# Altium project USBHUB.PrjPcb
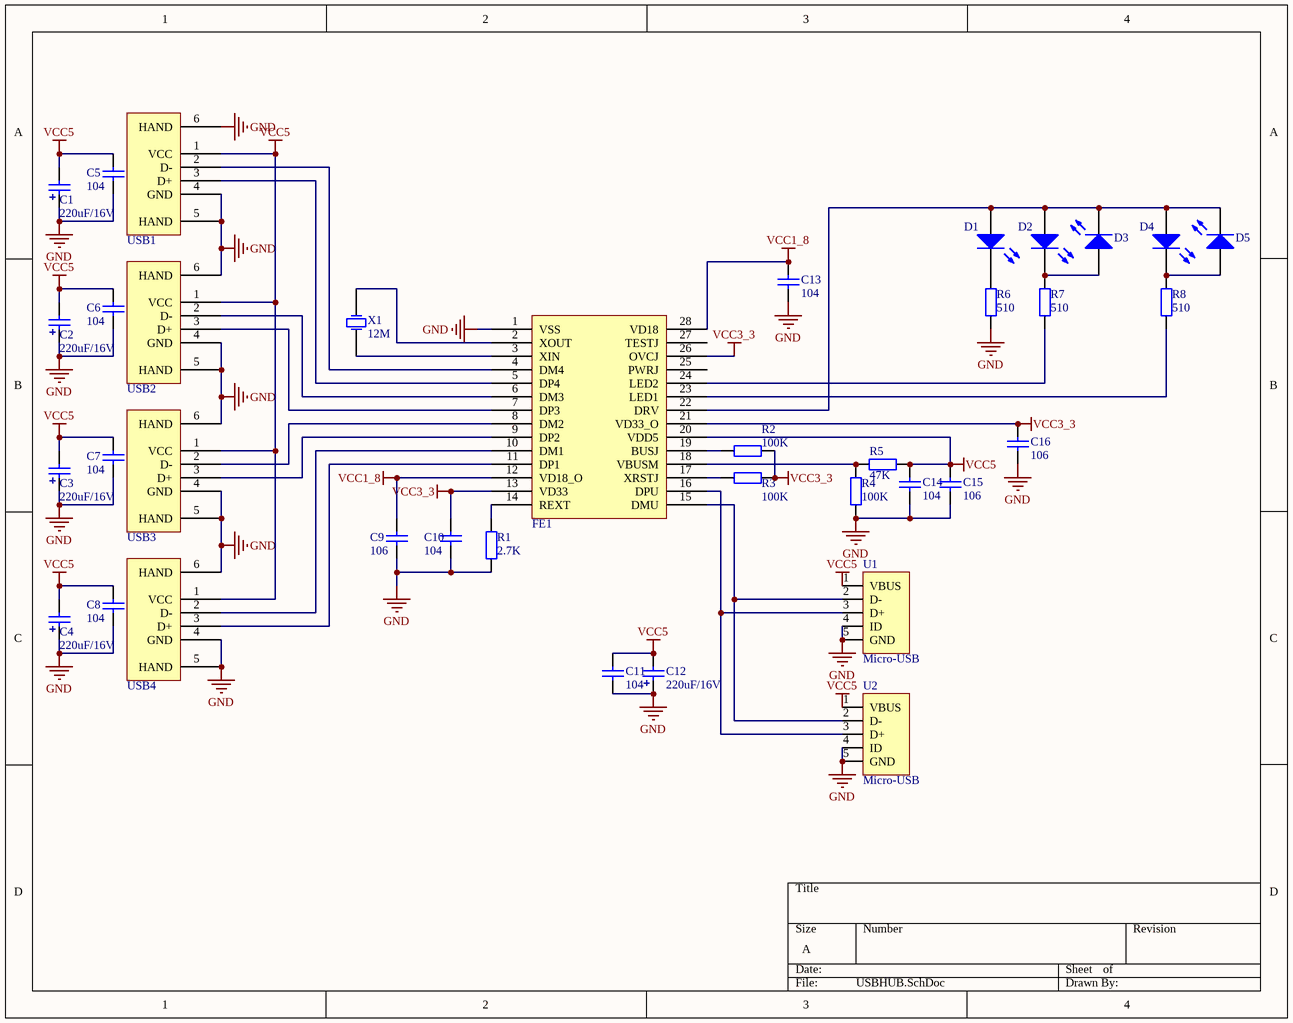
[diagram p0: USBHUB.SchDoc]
1 sheet, 37 parts. Net scope: global (net labels, ports and power ports of the same name join across sheets).
Board file: USBHUB.PcbDoc

## Sheet USBHUB.SchDoc
size A

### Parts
C1  value 220uF/16V  [cap_220uF/16V]  (hidden comment: Cap_Pol)
C2  value 220uF/16V  [cap_220uF/16V]  (hidden comment: Cap_Pol)
C3  value 220uF/16V  [cap_220uF/16V]  (hidden comment: Cap_Pol)
C4  value 220uF/16V  [cap_220uF/16V]  (hidden comment: Cap_Pol)
C5  value 104  [0603]  (hidden comment: Cap1)
C6  value 104  [0603]  (hidden comment: Cap1)
C7  value 104  [0603]  (hidden comment: Cap1)
C8  value 104  [0603]  (hidden comment: Cap1)
C9  value 106  [2012[0805]-C]  (hidden comment: Cap1)
C10  value 104  [0603]  (hidden comment: Cap1)
C11  value 104  [0603]  (hidden comment: Cap1)
C12  value 220uF/16V  [cap_220uF/16V]  (hidden comment: Cap_Pol)
C13  value 104  [0603]  (hidden comment: Cap1)
C14  value 104  [0603]  (hidden comment: Cap1)
C15  value 106  [2012[0805]-C]  (hidden comment: Cap1)
C16  value 106  [2012[0805]-C]  (hidden comment: Cap1)
D1  LED  [0603-Polar]  (value not drawn)
D2  LED  [0603-Polar]  (value not drawn)
D3  LED  [0603-Polar]  (value not drawn)
D4  LED  [0603-Polar]  (value not drawn)
D5  LED  [0603-Polar]  (value not drawn)
FE1  FE1.1s  [SSOP-28]  (value not drawn)
R1  value 2.7K  [0603]  (hidden comment: Res1)
R2  value 100K  [0603]  (hidden comment: Res1)
R3  value 100K  [0603]  (hidden comment: Res1)
R4  value 100K  [0603]  (hidden comment: Res1)
R5  value 47K  [0603]  (hidden comment: Res1)
R6  value 510  [0603]  (hidden comment: Res1)
R7  value 510  [0603]  (hidden comment: Res1)
R8  value 510  [0603]  (hidden comment: Res1)
U1  Micro-USB  [MICRO-USB-F]
U2  Micro-USB  [MICRO-USB-F]
USB1  USB  [USB2.5-2V4A]  (value not drawn)
USB2  USB  [USB2.5-2V4A]  (value not drawn)
USB3  USB  [USB2.5-2V4A]  (value not drawn)
USB4  USB  [USB2.5-2V4A]  (value not drawn)
X1  12M  [XTAL_SMD]

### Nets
GND: C1.1 C2.1 C3.1 C4.1 C5.1 C6.1 C7.1 C8.1 C9.1 C10.1 C11.1 C12.1 C13.2 C14.1 C15.1 C16.1 FE1.1(VSS) R1.1 R4.1 R6.1 U1.4(ID) U1.5(GND) U2.4(ID) U2.5(GND) USB1.4(GND) USB1.5(HAND) USB1.6(HAND) USB2.4(GND) USB2.5(HAND) USB2.6(HAND) USB3.4(GND) USB3.5(HAND) USB3.6(HAND) USB4.4(GND) USB4.5(HAND) USB4.6(HAND)
VCC1_8: C9.2 C13.1 FE1.12(VD18_O) FE1.28(VD18)
VCC3_3: C10.2 C16.2 FE1.13(VD33) FE1.21(VD33_O) FE1.26(OVCJ) R2.2 R3.2
VCC5: C1.2 C2.2 C3.2 C4.2 C5.2 C6.2 C7.2 C8.2 C11.2 C12.2 C14.2 C15.2 FE1.20(VDD5) R5.2 U1.1(VBUS) U2.1(VBUS) USB1.1(VCC) USB2.1(VCC) USB3.1(VCC) USB4.1(VCC)
NetD1_1: D1.1(A) D2.1(A) D3.2(K) D4.1(A) D5.2(K) FE1.22(DRV)
NetD1_2: D1.2(K) R6.2
NetD2_2: D2.2(K) D3.1(A) R7.2
NetD4_2: D4.2(K) D5.1(A) R8.2
NetFE1_2: FE1.2(XOUT) X1.2(OSC2)
NetFE1_3: FE1.3(XIN) X1.1(OSC1)
NetFE1_4: FE1.4(DM4) USB1.2(D-)
NetFE1_5: FE1.5(DP4) USB1.3(D+)
NetFE1_6: FE1.6(DM3) USB2.2(D-)
NetFE1_7: FE1.7(DP3) USB2.3(D+)
NetFE1_8: FE1.8(DM2) USB3.2(D-)
NetFE1_9: FE1.9(DP2) USB3.3(D+)
NetFE1_10: FE1.10(DM1) USB4.2(D-)
NetFE1_11: FE1.11(DP1) USB4.3(D+)
NetFE1_14: FE1.14(REXT) R1.2
NetFE1_15: FE1.15(DMU) U1.2(D-) U2.2(D-)
NetFE1_16: FE1.16(DPU) U1.3(D+) U2.3(D+)
NetFE1_17: FE1.17(XRSTJ) R3.1
NetFE1_18: FE1.18(VBUSM) R4.2 R5.1
NetFE1_19: FE1.19(BUSJ) R2.1
NetFE1_23: FE1.23(LED1) R8.1
NetFE1_24: FE1.24(LED2) R7.1

Not connected (* = marked no-connect by the designer): FE1 25(PWRJ) 27(TESTJ)

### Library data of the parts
C1-C4 C12 = Cap_Pol: Capacitor
C5-C11 C13-C16 = Cap1: Capacitor
D1-D5 = LED1: Typical INFRARED GaAs LED
R1-R8 = Res1: Resistor
X1 = XTAL_1: Crystal Oscillator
